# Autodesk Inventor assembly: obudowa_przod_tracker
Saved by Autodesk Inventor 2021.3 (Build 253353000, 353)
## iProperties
Created: 2023-01
Part Number: obudowa_przod_tracker
Document SubType Name: Assembly
Designer: AdminForWorker
Title: obudowa_przod_tracker v37
Author: AdminForWorker
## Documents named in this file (2)
- c:\worker\convert-fusion-r07-cosv3\tmp\job-1\151\output\files\831a58fd-8d39-4809-ab40-fed223814375\0de319ef-6fa5-4152-b6bd-cc91707e25dc.iam
- c:\worker\convert-fusion-r07-cosv3\tmp\job-1\151\output\files\831a58fd-8d39-4809-ab40-fed223814375\obudowa_przod_tracker_V6.iam
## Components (1 placed, 1 different names)
1. obudowa_przod_tracker_V6:1 [sub-assembly]
